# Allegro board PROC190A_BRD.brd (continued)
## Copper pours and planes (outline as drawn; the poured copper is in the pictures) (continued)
VDD_MMC0_SD on BOTTOM: 123.6,76.33 121.16,76.33 121.16,75.41 121.49,75.41 121.62,75.54 123.6,75.54
VDD_MMC0_SD on L04_PWR1: 122,76.53 121.11,76.53 120.62,76.05 120.62,75.34 119.33,74.04 114.73,74.04 113.41,75.36 111.84,75.36 111.63,75.16 111.63,73.63 112.22,73.05 120.52,73.05 122.35,74.88 122.35,76.17
VDDA1V8 on TOP: 32.14,53.62 32.14,54.51 34.19,54.51 34.34,54.66 35.1,54.66 35.48,54.28 35.48,52.93 35.64,52.78 37.19,52.78 37.62,53.21 37.62,54.12 37.78,54.28 38.9,54.28 38.96,54.22 38.96,50.6 39.57,49.99 41.25,49.99 41.5,49.73 41.5,49.02 41.33,48.84 38.33,48.84 37.64,49.53 37.64,51.55 37.27,51.92 35.43,51.92 33.73,53.62
VDDA1V8 on BOTTOM: 40.74,50.14 40.74,48.82 41.5,48.82 41.5,50.14
VDDA1V8 on L04_PWR1: 43.97,52.04 39.9,52.04 39.65,51.79 39.65,49.4 40.28,48.77 41.35,48.77 41.35,51.08 41.61,51.33 42.75,51.33 43.61,50.47 43.61,46.79 45.24,45.16 64.47,45.16 65.43,46.13 65.43,55.04 65.1,55.37 63.91,55.37 63.69,55.16 63.71,48.26 62.48,47.04 59.89,47.04 58.45,48.49 47.52,48.49
VDDA_1V8 on TOP: 41.58,54.25 41.58,52.4 41.27,52.1 41.27,51.56 41.07,51.36 39.28,51.36 39.28,54.25
VDDA_1V8 on TOP: 109.4,56.97 109.4,55.24 112.39,55.24 112.39,56.97
VDDA_1V8 on TOP: 72.11,73.03 72.44,72.69 72.44,70.61 71.78,69.95 71.78,69.01 71.96,68.83 73.46,68.83 73.94,68.35 73.94,67.67 73.36,67.08 72.9,67.08 72.62,66.8 72.62,66.14 72.82,65.94 74.07,65.94 74.55,66.42 74.55,69.22 73.2,70.56 73.2,73.13 72.95,73.38 72.95,73.71 72.69,73.96 72.21,73.96 72.11,73.86
VDDA_1V8 on BOTTOM: 69.01,75.26 68.05,75.26 68.02,75.23 68.02,74.63 68.05,74.6 68.91,74.6 69.22,74.3 69.22,72.9 69.52,72.59 72.31,72.59 72.59,72.87 73.63,72.87 74.22,72.29 78.11,72.29 78.31,72.09 78.31,71.3 78.38,71.22 78.99,71.22 79.04,71.27 79.04,72.36 78.59,72.82 74.8,72.82 73.66,73.96 71.73,73.96 71.75,73.99 71.75,74.22 71.7,74.27 71.15,74.27 71.02,74.14 71.02,73.15 70.97,73.1 69.95,73.1 69.82,73.23 69.82,74.45
VDDA_1V8 on BOTTOM: 108.58,56.85 108.58,55.58 111.3,55.58 111.3,56.85
VDDA_1V8 on BOTTOM: 63.65,66.62 64.34,65.94 73.46,65.94 73.74,66.22 73.74,66.9 72.85,67.79 69.47,67.79 69,67.32 64.83,67.32 64.66,67.5 64.66,68.14 64.41,68.38 63.78,68.38 63.65,68.25
VDDA_1V8 on BOTTOM: 58.52,78.94 57.81,78.94 57.73,78.87 57.73,78.11 57.78,78.05 57.78,77.52 57.94,77.37 58.42,77.37 58.55,77.5 58.55,78.92
VDDA_1V8 on L04_PWR1: 40.49,53.82 40.36,53.7 40.36,52.5 40.53,52.34 44.4,52.34 47.66,49.07 54.36,49.07 55.6,50.32 55.6,53.67 56.79,54.86 62.33,54.86 63.4,55.93 68.94,55.93 70.64,54.23 110.08,54.23 110.36,54.51 110.36,56.82 109.75,57.43 71.32,57.43 68.4,60.35 68.4,68.68 67.89,69.19 61.9,69.19 60.3,67.59 60.3,61.16 58.78,59.64 57.2,59.64 51.38,53.82
VDDA_1V8_FB1 on L04_PWR1: 75.03,71.3 75.03,85.12 73.53,86.61 68.76,86.61 68.12,85.98 67.49,85.98 67.06,85.55 66.57,85.55 66.57,86.79 66.7,86.92 68.1,86.92 69.34,88.16 78.05,88.16 79.04,87.17 79.04,71.3
VDDA_1V8_FB2 on L04_PWR1: 67.94,85.6 67.56,85.6 66.5,84.53 66.5,82.32 66.75,82.07 68.86,82.07 69.39,81.53 69.39,80.44 68.48,79.53 65.63,79.53 64.87,80.29 64.29,80.29 64.08,80.09 64.08,76 65.1,74.98 69.39,74.98 70.89,76.48 70.89,82.35 69.8,83.44 68,83.44 67.54,83.9 67.54,84.43 68.1,84.99 68.1,85.45
VDDA_1V8_FB3 on L03_SIG1: 62.99,81.71 62.64,81.71 62.33,81.41 62.33,65.91 63.3,65.91 63.53,66.14 63.53,81.18
VDDA_1V8_FB4 on L04_PWR1: 71.27,84.56 68.05,84.56 68.05,83.59 70.18,83.59 71.48,82.3 71.48,76.23 70.05,74.8 70.05,74.32 70.36,74.02 71.27,74.02 72.75,75.49 72.75,83.08
VDDA_1V8_FB_OSC on BOTTOM: 59.45,79.68 58.47,79.68 58.19,79.96 57.71,79.96 57.71,79.2 59.42,79.2 59.51,79.29 59.51,79.61
VDDA_ADC0 on L03_SIG1: 64.62,81.1 64.26,81.1 64.26,80.77 64.41,80.62 64.41,80.44 64.54,80.31 64.54,71.91 65.3,71.15 65.3,70.05 64.9,69.65 64.9,67.79 65.05,67.64 65.2,67.64 65.8,68.24 65.8,69.76 66.04,70 66.04,71.5 65.33,72.21 65.33,80.34 65.13,80.34 64.62,80.85
VDDA_CORE_USB on TOP: 74.07,98.15 72.64,98.15 72.64,96.27 72.78,96.13 72.78,92.65 72.9,92.53 73.28,92.53 73.46,92.71 73.46,94.13 74.07,94.74
VDDA_CORE_USB on L03_SIG1: 69.86,84.8 69.86,86.16 69.52,86.5 69.52,91.54 70.33,92.35 73.33,92.35 73.33,93.27 68.91,93.27 68.02,92.38 68.02,86.97 68.2,86.79 68.2,85.7 67.82,85.32 66.98,85.32 66.67,85.01 66.67,84.76 67.06,84.38 69.44,84.38
VDDR_CORE on TOP: 42.98,70.33 41.45,70.33 41.45,68.91 42.98,68.91
VDDR_CORE on BOTTOM: 38.45,64.38 38.45,62.18 41.27,62.18 41.27,64.38
VDDR_CORE on L03_SIG1: 64.34,82.85 64.74,82.45 67.03,82.45 67.03,84.18 66.88,84.33 66.32,84.33 66.14,84.51 66.14,85.47 66.61,85.94 67.68,85.94 67.92,86.18 67.92,86.61 67.44,87.1 67.44,88.98 67.16,89.26 65.15,89.26 64.94,89.04 64.94,87.9 64.69,87.66 63.07,87.66 61.72,86.31 60.96,86.31 60.55,86.72 60.27,86.72 59.89,87.1 57.71,87.1 57.33,86.72 54.76,86.72 54.08,86.03 54.08,84.51 54.53,84.05 58.34,84.05 58.52,84.23 63.32,84.23 63.5,84.4 63.88,84.4 64.34,83.95
VDDR_CORE on L04_PWR1: 47.04,76.15 43.21,72.31 42.62,72.31 41.53,71.22 41.53,67.89 40.69,67.06 40.69,66.08 39.32,64.71 39.32,62.69 39.88,62.13 41.43,62.13 43.43,64.14 43.43,68.5 49.53,74.6 51.16,74.6 54.94,78.38 54.94,80.44 55.88,81.38 55.88,84.84 55.65,85.06 54.18,85.06 52.83,83.72 50.16,83.72 47.04,80.59
VDDR_CORE_0V85 on BOTTOM: 36.93,65.1 36.93,65.76 37.19,66.01 41.12,66.01 41.17,65.96 41.17,64.92 41.02,64.77 38.05,64.77 37.92,64.9 37.13,64.9
VDDSHV_CANUART on TOP: 38.38,35.89 35.46,35.89 35.26,35.69 35.26,35.23 35.43,35.05 38.35,35.05 38.58,35.28 38.58,35.69
VDDSHV_CANUART on TOP: 29.59,155.78 28.91,155.78 28.75,155.63 28.75,150.88 32.23,147.4 32.74,147.4 33.07,147.73 33.07,148.29 29.69,151.66 29.69,155.68
VDDSHV_CANUART on TOP: 15.95,51.21 18.62,51.21 19.02,50.8 19.02,49.5 19,49.48 18.41,49.48 18.39,49.5 18.39,50.5 18.14,50.75 15.93,50.75 15.93,51.18
VDDSHV_CANUART on TOP: 13,51.66 13,53.09 12.85,53.24 12.27,53.24 12.12,53.09 12.12,51.77 12.22,51.66
VDDSHV_CANUART on TOP: 38.38,66.52 38.38,62.69 38.46,62.61 38.89,62.61 39.09,62.81 39.09,65.28 41.71,67.89 42.42,67.89 42.52,67.79 42.52,67.06 42.24,66.78 42.24,58.78 42.01,58.55 42.01,52.32 41.48,51.79 41.48,50.77 41.71,50.55 41.99,50.55 42.29,50.85 42.29,51.28 42.55,51.54 42.55,57.91 43.15,58.52 43.15,68.2 42.75,68.61 41.2,68.61 40.18,67.59 39.45,67.59
VDDSHV_CANUART on TOP: 29.54,159.66 31.06,159.66 31.9,160.5 32.94,160.5 33.17,160.27 33.17,159.59 32.79,159.21 29.57,159.21 29.44,159.33 29.44,159.56
VDDSHV_CANUART on TOP: 43.54,83.03 43.13,83.44 43.13,84.25 39.65,87.73 39.65,100.23 40.36,100.94 44.04,100.94 45.26,102.16 45.26,114.66 46.63,116.03 46.63,120.57 47.5,121.44 50.67,121.44 51.08,121.03 56.08,121.03 56.34,120.78 57.78,120.78 58.12,121.11 58.12,124.64 58.01,124.74 56.54,124.74 56.44,124.64 56.44,124.1 56.69,123.85 57.33,123.85 57.66,123.52 57.66,121.39 57.51,121.23 56.9,121.23 56.46,121.67 55.98,121.67 55.8,121.84 55.8,122.15 55.4,122.56 54.15,122.56 53.87,122.83 52.25,122.83 51.97,122.56 46.76,122.56 45.49,121.28 45.49,116.08 44.63,115.21 44.63,102.87 43.79,102.03 40.49,102.03 39.01,100.56 39.01,87.1 42.49,83.62 42.49,83.03 43.68,81.85 44.54,81.85 44.96,82.27 44.96,82.85 44.78,83.03
VDDSHV_CANUART on TOP: 11.1,11.89 10.41,11.89 10.36,11.84 10.36,11.02 11.18,10.21 15.88,10.21 17.96,12.29 17.96,13.34 23.52,18.9 23.52,24.38 17.37,30.53 17.37,35.26 15.47,37.16 15.47,44.93 15.85,45.31 15.85,46.96 15.67,47.14 14.76,47.14 14.61,46.99 14.61,44.6 14.81,44.4 14.81,35.2 16.74,33.27 16.74,29.97 22.78,23.93 22.78,19.81 17.04,14.07 17.04,12.47 15.42,10.85 11.46,10.85 11.1,11.2
VDDSHV_CANUART on TOP: 9.88,63.2 12.04,63.2 12.75,62.48 12.75,61.24 11.94,60.43 10.59,60.43 10.44,60.58 10.44,60.88 10.52,60.96 11.51,60.96 11.61,61.06 11.61,62.51 11.51,62.61 9.88,62.61 9.83,62.66 9.83,63.14
VDDSHV_CANUART on BOTTOM: 35.03,83.85 34.87,83.69 34.87,81.1 35,80.98 36.32,80.98 36.53,80.77 36.53,78.66 37.24,77.95 40.21,77.95 40.28,78.03 40.28,78.54 40.18,78.64 38.91,78.64 38.3,79.25 38.3,82.4 38.47,82.56 39.41,82.56 40.01,83.16 40.87,83.16 41.5,82.52 43.18,82.52 43.33,82.37 43.33,80.82 43.54,80.62 45.36,80.62 45.47,80.72 45.47,81.28 45.29,81.46 45.29,83.54 44.98,83.85
VDDSHV_CANUART on BOTTOM: 9.19,63.25 7.39,63.25 7.16,63.02 7.16,62.03 7.39,61.8 8.84,61.8 9.12,62.08 9.98,62.08 10.36,61.7 10.36,60.48 11.68,59.16 11.68,53.39 12.45,52.63 16.41,52.63 17.22,51.82 17.22,48.44 14.76,45.97 14.76,45.49 15.04,45.21 15.44,45.21 18.67,48.44 18.67,51.77 16.89,53.54 14.3,53.54 12.78,55.07 12.78,60.63 10.52,62.89 10.52,66.4 12.93,68.81 20.35,68.81 21.49,69.95 24.94,69.95 27.3,67.59 32.28,67.59 32.87,67.01 37.39,67.01 38.15,66.24 40.06,66.24 40.16,66.34 40.16,66.88 39.94,67.09 38.16,67.09 37.41,67.84 32.82,67.84 32.49,68.17 27.89,68.17 25.4,70.66 21.26,70.66 20.19,69.6 12.62,69.6 9.8,66.78 9.8,63.86
VDDSHV_CANUART on BOTTOM: 35.08,160.45 31.6,160.45 31.11,159.97 31.11,159.36 31.39,159.08 34.92,159.08 35.08,159.23
VDDSHV_CANUART on BOTTOM: 42.8,36.02 40.11,36.02 39.37,36.75 38.13,36.75 38,36.63 38,35.99 37.87,35.86 37.87,35.46 37.97,35.36 38.28,35.36 38.43,35.51 38.43,36.12 38.56,36.25 39.17,36.25 40.08,35.33 42.8,35.33
VDDSHV_CANUART on BOTTOM: 36.53,35.81 34.39,35.81 33.99,35.41 33.99,33.45 34.54,32.89 36.55,32.89 36.6,32.84 37.8,32.84 37.8,33.07 37.74,33.12 36.75,33.12 36.55,33.32 36.55,33.45 36.53,33.48 34.92,33.48 34.59,33.81 34.59,34.92 34.9,35.23 35.94,35.23 36.02,35.31 36.55,35.31 36.6,35.36 36.6,35.74
VDDSHV_CANUART on L03_SIG1: 28.47,156.29 28.47,155.4 28.88,154.99 29.95,154.99 32.79,157.84 32.79,159.59 32.04,160.34 30.84,160.34 30.03,159.53 30.03,157.84
VDDSHV_CANUART on L04_PWR1: 40.34,78.84 39.17,78.84 38.86,78.54 38.86,77.01 39.8,76.07 39.8,71.96 38.4,70.56 38.4,66.12 38.79,65.74 39.6,65.74 40.08,66.22 40.08,67.41 41.02,68.35 41.02,71.63 42.24,72.85 43,72.85 46.48,76.33 46.48,82.27 45.59,83.16 43.54,83.16 43.08,82.7 43.08,81.89 44.4,80.57 44.4,77.17 44.04,76.81 41.68,76.81 40.49,78 40.49,78.69
VDDSHV_CANUART on L04_PWR1: 41.57,50.84 41.57,50.58 41.68,50.47 41.68,48.41 40.97,47.7 40.97,35.31 41.25,35.03 42.47,35.03 42.8,35.36 42.8,38.4 43.26,38.86 43.26,46.15 42.9,46.51 42.9,50.44 42.34,51 41.73,51
VDDSHV_CANUART on L04_PWR1: 33.22,148.29 32.64,148.29 31.29,146.94 31.29,128.96 34.7,125.55 46.15,125.55 49.56,122.15 52.6,122.15 52.76,122.3 52.76,124.61 50.34,127.03 34.98,127.03 32.61,129.39 32.61,146.41 33.68,147.47 33.68,147.83
VDDSHV_SDIO on TOP: 34.52,56.47 35.21,56.47 35.41,56.26 35.41,55.12 35.26,54.97 34.16,54.97 33.89,55.25 33.89,55.5 34.29,55.91 34.29,56.24
VDDSHV_SDIO on BOTTOM: 35.56,57.28 34.37,57.28 34.37,55.52 34.8,55.09 35.56,55.09
(no net) on TOP: 1.02,1.02 1.02,175.98 125.98,175.98 125.98,1.02 ; 226 cut-outs
(no net) on BOTTOM: 1.02,1.02 1.02,175.98 125.98,175.98 125.98,1.02 ; 212 cut-outs
(no net) on L03_SIG1: 1.02,1.02 1.02,175.98 125.98,175.98 125.98,1.02 ; 204 cut-outs
ADC0_REFN on BOTTOM: 63.91,75.97 63.47,75.97 63.32,75.82 63.32,75.56 63.63,75.26 63.63,72.92 63.7,72.85 64.29,72.85 64.36,72.92 64.36,73.74 64.21,73.89 64.21,75.67
ADC0_REFP on BOTTOM: 63.37,75.31 62.99,75.31 62.61,74.93 62.61,73.69 62.76,73.53 63.3,73.53 63.45,73.69 63.45,75.23
DRAIN1 on TOP: 27.33,19.41 27.33,17.43 29.84,17.43 29.84,19.41
DRAIN1 on BOTTOM: 25.82,16.96 25.82,17.62 26.1,17.9 27.07,17.9 27.19,18.02 27.19,19.22 26.35,19.22 26.35,19.5 29.83,19.5 29.83,17.77 29.68,17.62 27.27,17.62 27.17,17.51 26.66,17.51 26.58,17.44 26.58,16.96
DRAIN2 on TOP: 30.25,19.41 30.25,17.43 33.07,17.43 33.07,19.41
DRAIN2 on BOTTOM: 33.68,16.96 33.5,17.14 33.5,17.44 33.42,17.51 33.08,17.51 32.98,17.62 30.4,17.62 30.25,17.77 30.25,19.5 33.77,19.5 33.77,19.22 32.93,19.22 32.89,19.17 32.89,17.95 33.93,17.95 34.26,17.62 34.26,17.04 34.18,16.96 ; 1 cut-out
FT4232_USB_VBUS on TOP: 55.07,4.97 55.07,6.96 54.14,7.89 54.14,8.46 50.29,8.46 49.79,8.97 49.44,8.97 49.41,8.94 49.41,8.24 48.7,8.24 48.61,8.33 48.61,8.94 48.51,9.03 48.05,9.03 47.91,8.9 47.91,7.42 48.02,7.3 52.98,7.3 53.56,6.72 53.56,5.7 54.3,4.97
LM61460_BOOT on TOP: 4.04,14.66 4.04,14.22 5.99,14.22 6.68,14.91 7.59,14.91 7.59,15.14 6.78,15.14 6.3,14.66
LM61460_FB on TOP: 9.55,14.68 9.14,14.68 9.14,13.44 9.6,12.98 9.6,11.66 9.14,11.2 7.9,11.2 7.9,10.34 9.98,10.34 10.16,10.16 10.16,9.7 10.52,9.35 11.61,9.35 11.61,9.91 11.02,9.91 9.98,10.95 9.98,13.23 9.55,13.67
LM61460_SW on TOP: 9.4,15.75 8.26,15.75 8.26,20.19 7.67,20.78 5.92,20.78 5.28,21.41 5.28,23.32 5.69,23.72 12.98,23.72 13.34,23.37 13.34,21.79 12.73,21.18 10.85,21.18 9.4,19.74
MIC1_BIAS on TOP: 59,163.4 65.63,163.4 65.89,163.65 65.89,164.11 65.74,164.26 58.85,164.26 58.75,164.16 58.75,163.65
MIC1_BIAS on TOP: 70.38,171.58 66.12,171.58 65.53,170.99 65.15,170.99 64.38,170.22 64.38,170.09 64.59,169.88 65.02,169.88 65.84,170.69 69.47,170.69 70.89,169.27 70.89,165.13 70.31,164.54 70.31,160.05 68.55,158.29 68.55,155.91 67.16,154.51 67.16,147.83 68.5,146.48 69.32,146.48 69.49,146.66 69.49,147.04 69.32,147.22 68.96,147.22 67.79,148.39 67.79,153.95 69.42,155.57 69.42,157.53 71.78,159.89 71.78,170.18
MIC1_BIAS on BOTTOM: 58.03,146.74 58.03,144.86 57.95,144.77 56.52,144.77 56.29,145 56.29,146.99 57.56,148.26 62.59,148.26 63.65,147.19 69.47,147.19 69.65,147.02 69.65,146.53 69.24,146.13 63.17,146.13 62.14,147.15 58.45,147.15
MIC1_BIAS on BOTTOM: 59.26,170.69 70.18,170.69 71.12,169.75 71.12,163.98 69.44,162.31 62.23,162.31 61.16,163.37 61.16,164.21 61.39,164.44 62.56,164.44 63.65,163.35 68.1,163.35 69.52,164.77 69.52,168.35 68.17,169.7 65.86,169.7 65.23,169.06 59.31,169.06 59.26,169.11
MIC2_BIAS on TOP: 42.88,150.37 42.88,151.41 42.67,151.61 42.67,151.99 42.77,152.1 43.21,152.1 43.36,151.94 43.36,150.44 43.28,150.37
MIC2_BIAS on TOP: 41.81,163.45 48.49,163.45 48.74,163.7 48.74,164.24 48.49,164.49 41.81,164.49 41.55,164.24 41.55,163.7
MIC2_BIAS on BOTTOM: 51.66,170.79 42.04,170.79 41.83,170.59 41.83,169.42 42.14,169.11 48.29,169.11 48.79,169.62 50.57,169.62 52.65,167.54 52.65,165.68 51.51,164.54 49.63,164.54 48.46,163.37 45.69,163.37 44.81,164.26 44.37,164.26 44.2,164.08 44.2,163.19 44.75,162.64 50.14,162.64 50.99,163.49 51.98,163.49 53.82,165.33 53.82,168.63
MIC2_BIAS on BOTTOM: 41.79,153.25 43.59,153.25 43.72,153.12 43.72,151.89 43.15,151.31 42.11,151.31 41.76,151.67 41.76,153.22
MIC2_BIAS on L03_SIG1: 43.92,160.55 42.39,159.03 42.39,151.66 42.8,151.26 43.05,151.26 43.56,151.76 43.56,158.6 45.34,160.38 45.34,164.11 45.11,164.34 45.11,165.71 48.39,168.99 48.39,170.23 48.01,170.61 45.14,170.61 43.92,169.39
PCM1_BSTOUT on TOP: 57.68,143.7 57.68,145.58 57.08,145.58 57.08,146 56.2,146 56.14,145.94 56.14,145.88 56.13,145.87 57.06,144.94 57.06,144.63 57.11,144.58 57.11,143.71 57.68,143.71
SOC_DVDD1V8 on TOP: 29.05,42.01 29.05,43.55 24.38,43.55 24.38,42.01
SOC_DVDD1V8 on L03_SIG1: 63.63,80.62 63.47,80.77 63.47,81.66 63.17,81.97 62.03,81.97 61.87,82.12 61.87,82.68 61.59,82.96 61.01,82.96 60.53,82.47 54.31,82.47 53.57,83.21 52.73,83.21 51.69,84.25 51.69,88.27 52.8,89.37 60.64,89.37 61.06,89.79 61.06,91.26 61.42,91.62 63.47,91.62 63.8,91.29 63.8,90.7 64.74,89.76 64.74,87.83 62.84,87.83 61.62,86.61 60.78,86.61 60.25,87.15 53.92,87.15 53.19,86.41 53.19,84.84 54.33,83.69 60.83,83.69 61.16,84.02 62.94,84.02 63.86,83.11 63.86,82.17 64.19,81.84 65.81,81.84 66.34,81.31 66.34,80.82 66.19,80.67 65.3,80.67 64.67,81.31 64.19,81.31 64.06,81.18 64.06,80.85 63.83,80.62
SOC_DVDD1V8 on L04_PWR1: 20.07,51.26 23.93,47.4 23.93,42.8 24.05,42.67 25.25,42.67 25.5,42.93 25.5,50.27 23.11,52.65 23.11,57.23 31.01,65.13 31.8,65.13 34.52,67.84 34.52,82.65 38.96,87.1 49.23,87.1 52.08,84.24 52.62,84.24 53.26,84.89 53.26,85.24 51.03,87.48 51.03,88.39 49.43,89.99 37.62,89.99 32.03,84.4 32.03,69.19 31.01,68.17 21.08,68.17 20.07,67.16
SOC_DVDD3V3 on TOP: 42.85,52.27 42.85,57.48 44.42,57.48 44.42,52.27
SOC_DVDD3V3 on L04_PWR1: 73.2,83.41 71.45,85.17 68.73,85.17 68.35,85.55 68.35,85.72 68.86,86.23 73,86.23 74.55,84.68 74.55,71.5 73.03,69.98 61.65,69.98 59.54,67.87 59.54,61.06 58.7,60.22 54.66,60.22 49.63,55.19 46.63,55.19 46.22,54.78 43.62,54.78 43.31,55.09 43.31,56.02 43.67,56.39 45.16,56.39 52.2,63.42 56.85,63.42 57.94,64.52 57.94,69.93 58.32,70.31 58.32,77.27 60.35,79.3 61.87,79.3 62.43,79.86 62.43,80.01 62.69,80.26 63.25,80.26 63.55,79.96 63.55,75.46 65.76,73.25 72.11,73.25 73.2,74.35
SOC_DVDD3V3_FB1 on BOTTOM: 68.83,83.95 68.83,83.31 71.45,83.31 72.29,84.15 72.29,85.22 70.41,85.22 70.41,84.07 70.28,83.95
SOC_VDD_CANUART on TOP: 51.64,79.35 51.74,79.25 51.74,78.71 47.02,78.71 46.2,77.9 46.2,76.73 44.78,76.73 44.7,76.81 44.7,79.22 44.83,79.35
SOC_VDD_CANUART on L03_SIG1: 61.93,81.28 61.42,81.28 59.13,78.99 52.68,78.99 52.22,79.45 51.26,79.45 50.98,79.17 50.98,78.28 51.41,77.85 59.84,77.85 60.17,78.18 60.17,79.2 61.37,80.39 61.93,80.39
SOC_VDDSHV5_SDIO on L03_SIG1: 69.16,84.2 68.25,84.2 68.15,84.1 68.15,82.4 66.93,81.18 66.93,80.85 66.27,80.19 66.27,74.98 67.28,73.96 67.87,73.96 68.12,74.22 68.12,74.93 67.51,75.54 67.51,79.68 69.49,81.66 69.49,83.87
SOC_VDDSHV_CANUART on BOTTOM: 53.64,82.65 53.29,82.65 53.01,82.37 50.8,82.37 50.11,81.69 47.62,81.69 47.02,82.3 47.02,82.75 47.55,83.29 47.55,84.66 46.44,85.76 35.13,85.76 33.27,83.91 33.27,81.1 33.38,81 34.47,81 34.62,81.15 34.62,83.92 34.92,84.23 45.11,84.23 45.59,83.74 45.59,81.51 47.02,80.09 50.01,80.09 51.77,81.84 53.29,81.84 53.77,82.32 53.77,82.52
SOC_VDDSHV_CANUART on L03_SIG1: 61.44,82.65 61.16,82.65 60.66,82.14 54.18,82.14 53.67,82.65 53.14,82.65 52.7,82.22 52.7,81.79 53.52,80.98 54.61,80.98 54.97,80.62 58.27,80.62 58.7,81.05 60.76,81.05 60.96,81.25 60.96,81.76 61.57,82.37 61.57,82.52
SW_2V5 on BOTTOM: 83.09,31.65 81.62,31.65 81.62,31.44 82.94,31.44 83.43,30.96 85.6,30.96 85.6,32.21 83.65,32.21
UART_SHIELD on TOP, BOTTOM, L02_GND1, L03_SIG1, L04_PWR1, L05_GND2: 62.59,3.78 62.59,1.36 62.25,1.02 51.87,1.02 51.67,1.21 51.67,6.35 52.08,6.76 52.79,6.76 53.18,6.37 53.18,4.99 53.08,4.89 53.08,3.96 53.46,3.58 58.84,3.58 59.34,4.08 59.34,4.66 59.17,4.82 59.17,6.34 59.54,6.71 60.26,6.71 61.32,5.64 61.32,4.59 61.75,4.16 62.2,4.16
USB_TYPEC1_EARTH on TOP, BOTTOM, L02_GND1, L03_SIG1, L04_PWR1, L05_GND2: 30.23,1.02 17,1.02 17,8.23 20.29,8.23 20.55,7.98 20.55,4.27 21.06,3.77 27.76,3.77 28.21,4.23 28.21,7.94 28.51,8.23 30.23,8.23
USB_TYPEC2_EARTH on TOP, BOTTOM, L02_GND1, L03_SIG1, L04_PWR1, L05_GND2: 45.23,1.02 32,1.02 32,8.23 35.29,8.23 35.55,7.98 35.55,4.27 36.06,3.77 42.76,3.77 43.21,4.23 43.21,7.94 43.51,8.23 45.23,8.23
VMAIN on TOP: 19.76,20.65 16.41,20.65 15.72,19.96 15.72,18.67 15.44,18.39 13.87,18.39 13.03,17.55 11.33,17.55 10.82,17.04 9.7,17.04 9.7,16.13 9.86,15.98 17.7,15.98 18.75,17.02 18.75,18.21 19.13,18.59 19.13,19.43 19.76,20.07
VMAIN on TOP: 28.32,160.25 27.99,160.25 27.84,160.1 27.84,159.89 27.61,159.66 26.52,159.66 26.52,159.33 27.66,159.33 27.84,159.16 27.84,158.88 27.99,158.72 28.35,158.72 28.42,158.8 28.42,160.15
VMAIN on TOP: 7.87,17.17 5.13,17.17 4.65,17.65 2.44,17.65 2.44,15.98 4.24,15.98 4.47,16.21 5.82,16.21 6.02,16.41 7.87,16.41
VMAIN on BOTTOM: 18.29,20.9 14.5,20.9 14.5,16.81 18.29,16.81
VMAIN on BOTTOM: 2.74,17.5 2.74,14.96 9.32,14.96 9.32,17.5
VMAIN on BOTTOM: 28.52,160.2 28.07,160.2 27.61,159.74 26.82,159.74 26.72,159.64 26.72,158.98 27,158.7 28.45,158.7 28.52,158.78
VMAIN on L04_PWR1: 17.63,20.17 13.44,20.17 10.21,23.39 10.21,44.53 5.33,49.4 5.33,103.43 3.07,105.69 3.07,138.91 19.71,155.55 25.73,155.55 29.03,158.85 29.03,166.17 28.19,167 9.3,167 1.24,158.95 1.24,16.43 2.92,14.76 17.17,14.76 17.63,15.21
VMAIN_PD on TOP: 27.45,13.84 27.45,14.86 27.88,15.29 27.88,16.31 27.93,16.36 28.77,16.36 28.82,16.31 28.82,14.97 28.66,14.81 28.66,13.84
VMAIN_PD on TOP: 32.54,14.01 32.54,16.25 32.67,16.38 34.7,16.38 34.83,16.26 34.83,15.7 35.24,15.28 35.24,14.01
VMAIN_PD on TOP: 18.97,24.75 16.97,24.75 16.97,22.96 17.06,22.87 17.59,22.87 18.26,22.2 19.51,22.2 19.51,23.28 19,23.79 19,24.72
VMAIN_PD on BOTTOM: 28.85,17.48 28.12,17.48 28.09,17.45 28.09,16.43 27.89,16.23 27.89,14.99 27.94,14.94 28.78,14.94 28.85,15.01
VMAIN_PD on BOTTOM: 32.13,16.59 32.13,17.41 32.82,17.41 33.6,16.64 34.41,16.64 34.59,16.46 34.59,15.57 34.41,15.39 32.68,15.39 32.53,15.54 32.53,16.19
VMAIN_PD on L03_SIG1: 34.82,16.94 32.38,16.94 32.31,16.87 32.31,15.42 31.7,14.81 29.64,14.81 28.98,15.47 28.98,16.64 25.96,16.64 25.55,16.23 22.96,16.23 22.35,16.84 22.35,22.63 22.81,23.09 22.81,24.49 22.56,24.74 13.51,24.74 12.9,24.13 12.9,12.88 14.38,11.4 25.07,11.4 25.96,10.52 33.4,10.52 34.82,11.94
VPP_1V8 on TOP: 53.64,66.19 54.36,66.19 54.58,65.96 55.83,65.96 56.06,65.74 56.06,65.43 55.7,65.07 53.67,65.07 53.64,65.1
VPP_1V8 on L03_SIG1: 60.63,79.17 60.63,78.21 59.56,77.14 59.56,70.43 55.7,66.57 55.68,66.57 55.58,66.47 55.58,65.56 55.7,65.43 56.85,65.43 61.16,69.75 61.16,76.05 61.9,76.78 61.9,79.53 62.1,79.73 62.1,80.09 61.7,80.09 61.65,80.04 61.65,79.93 61.42,79.71 61.16,79.71
VPP_SUPPLY on TOP: 51.94,61.82 51.08,61.82 51.05,61.85 51.05,63.02 51.59,63.55 51.59,66.14 51.69,66.24 52.86,66.24 53.01,66.09 53.01,65.2 52.73,64.92 52.25,64.92 52.12,64.8 52.12,62.71 51.94,62.53
XDS_SHIELD on TOP, BOTTOM, L02_GND1, L03_SIG1, L05_GND2: 1.06,45.29 6.48,45.29 6.89,45.7 6.89,46.83 6.54,47.17 5.06,47.17 4.82,46.93 4.14,46.93 3.78,47.28 3.78,52.72 4.08,53.02 4.9,53.02 4.96,52.96 6.31,52.96 6.75,53.39 6.75,54.11 6.29,54.57 1.06,54.57
XDS_SHIELD on BOTTOM: 4.84,58.7 4.85,58.69 4.85,55.4 4.87,55.38 4.87,54.57 6.29,54.57 6.75,54.11 6.75,53.39 6.31,52.96 4.96,52.96 4.9,53.02 4.08,53.02 3.78,52.72 3.78,47.28 4.14,46.93 4.82,46.93 5.06,47.17 6.54,47.17 6.89,46.83 6.89,45.7 6.48,45.29 1.02,45.29 1.02,58.02 1.7,58.7
XDS_USB_VBUS on TOP: 5,51.03 6.35,51.03 7.16,51.84 8.48,51.84 8.99,51.33 8.99,50.6 9.07,50.52 10.26,50.52 10.72,50.98 10.72,52.58 10.69,52.6 5.31,52.6 5,52.3
XDS_USB_VBUS on TOP: 18.8,76.07 18.8,75.03 18.85,74.98 20.32,74.98 20.62,74.68 20.62,74.17 21.47,74.17 21.41,74.23 21.41,75.77 20.22,75.77 19.68,76.3 19.02,76.3
XDS_USB_VBUS on BOTTOM: 18.01,82.73 17.42,82.73 17.2,82.5 17.2,80.82 18.08,79.93 20.57,79.93 20.78,80.14 20.78,80.47 20.52,80.72 18.52,80.72 18.08,81.15 18.08,82.65
XDS_USB_VBUS on BOTTOM: 9.93,50.7 9.32,51.31 9.32,57.51 2.03,64.8 2.03,72.59 2.84,73.41 10.87,73.41 12.67,75.21 21.46,75.21 21.46,73.48 19.86,73.48 18.85,72.47 18.85,71.6 11.56,71.6 11.02,72.14 4.9,72.14 3.96,71.2 3.96,64.64 11.07,57.53 11.07,50.88 10.9,50.7
N24605846 on TOP: 55.49,146.36 55.49,143 56.82,143 56.82,144.81 55.96,145.67 55.96,147.39 55.5,147.39 55.5,146.36
N25809420 on TOP: 72.13,42.98 72.87,42.24 72.87,38.69 72.97,38.58 72.97,36.32 73.63,35.66 81.15,35.66 82.75,37.26 82.75,38.68 82.75,38.69 82.75,42.59 83.13,42.98 85.32,42.98 85.32,36.73 82.52,33.93 72.03,33.93 70.59,35.38 70.59,42.98
N25809420 on BOTTOM: 83.11,41.26 86.09,41.26 86.09,38.64 83.21,38.64 83.21,40.46 82.94,40.73 82.94,41.08
N25815350 on TOP: 104.62,43.2 105.3,42.53 105.3,38.14 104.19,37.03 104.19,35 105.28,33.91 113.28,33.91 115.18,35.8 115.18,42.68 115.56,43.07 117.93,43.07 117.93,36.02 114.45,32.54 104.57,32.54 102.54,34.57 102.54,43.2
N25815350 on BOTTOM: 102.88,41.26 104.96,41.26 105.1,41.13 105.1,40.29 104.72,39.91 104.72,38.71 104.59,38.58 103.03,38.58 102.8,38.81 102.8,39.5 102.65,39.65 102.65,41.03
N27162147 on BOTTOM: 43.1,14.24 43.1,15.53 43.27,15.7 45.53,15.7 45.53,18.23 42.54,18.23 42.51,18.21 42.51,14.24
N27162183 on TOP: 41.01,15.7 41.01,13.92 46.05,13.92 46.05,15.7
N27162183 on BOTTOM: 39.84,15.4 39.84,16.44 42.09,16.44 42.21,16.32 42.21,14 40.96,14 40.96,14.46 40.02,15.4
N27162293 on BOTTOM: 39.53,15.28 39.53,16.36 36.43,16.36 36.43,15.37 36.53,15.28
N27175987 on TOP: 81.03,57.52 82.42,57.52 82.72,57.22 83.43,57.22 83.6,57.39 83.6,59.79 83.47,59.92 82.89,59.92 82.85,59.88 82.85,58.65 82.51,58.31 81.07,58.31 81.01,58.25 81.01,57.54
N27224561 on TOP: 43.83,150.41 43.83,151.36 43.92,151.44 43.92,152.2 42.82,153.29 42.82,154.84 44.37,154.84 44.37,150.39 43.85,150.39 43.85,150.41

Small or netless copper shapes (teardrops, artwork), in the pictures only: 19 on TOP, 23 on BOTTOM, 23 on L03_SIG1

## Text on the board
Ref Des/Assembly Bottom: A | BOTTOM  ASSEMBLY OF PROC190A
Ref Des/Silkscreen Bottom: A | uSD_CONN | ASSY# | FOR EVALUATION ONLY; | NOT FCC APPROVED FOR RESALE
User.Comments: BOARD NAME: | AM275 EVM | REV: A | DATE: 28/02/25 | DESCRIPTION: | SHEET | OF | 13 | PROC190A | SCALE: 1 | TEXAS INSTRUMENTS
Ref Des/Assembly Top: TOP ASSEMBLY OF PROC190A
Ref Des/Silkscreen Top: JTAG_CONN | VCC3V3_XDS | AEC2 | SOC_DVDD1V8 | CAN_WKUP_HDR | INT | DGND | VDD_CORE | VBUS_TYPEC1 | WAIT-IN-RESET | PMIC_CORE_CONFIG | MCU_RESETz | VDDR_CORE_PWR_LED | VCC_3V3_SYS_PWR_LED | SOC_VDDSHV_CANUART | CORE_CONFIG | PMIC_RSTOUT_LED | VDDR_CORE | MCU WARM RST | SOC_DVDD3V3 | PMIC_RSTOUT | LINE_IN_2 | VCC_5V0 | VPP_1V8 | UART_CONN | BOOTMODEON_HDR | LINE_IN_1 | LINE_OUT_1 | RESETSTATZ_1V8 | ETHO_CONN | MCU_PORZ_HDR | PORz | LINE_OUT_2 | MMC0_SEL | MLB_HDR | VDD_2V5 | ADC_REFP_VSEL | ETH1_CONN | AEC1 | VDD_MMC0_SD | ADC0_HDR | PMIC_LPM_SEL | PD_PGM | USB-C PWR | MCAN0_HDR | VBUS_TYPEC1_PWR_LED | XDS_USB_VBUS | PWR ERROR | INDICATION LED | JTAG_CTI | VBUS_TYPEC2_PWR | EEPROM_WP_HDR | FT_PWREN#_LED | VBUS_TYPEC2 | VDDA_1V8 | USB-C DRP | IO RET WAKE | SOC_VDD_CANUART | VBAT_IN | BMODE 0-7 | SoC_GPIO_LED | IO EXP GPIO LED | BMODE 8-15 | MLB_VSEL_HDR | AUDIO-AM275-EVM | PROC190A | AM275 EVM | SL# | OPN#
PAGE_OUTLINE: 16. | 17. | ENSURE UL REGISTERED E-FILE NUMBER SHALL BE PRINTED ON THE PCB SILKSCREEN. | VIA ON PAD SHALL BE TYPE-VI FILLED. | REVIEWED BY | APPROVED BY | LAYOUT BY | SIGNATURES | UD | ZA | PANDI | 280225 | DATE | SIZE | SCALE: | D | NONE | SHEET 1 OF 23 | PROC190A | Rev | A | TEXAS INSTRUMENTS | AM275 EVM
User.12: R33 | C26 | H3 | H4 | R21 | R22 | R24 | R25 | R27 | R28 | R30 | J40 | R31 | R15 | R13 | R16 | R14 | R3 | R1 | R4 | R2 | R18 | C23 | C22 | R17 | C17 | R19 | C24 | C25 | R20 | R23 | R26 | R29 | R32 | 8
User.13: ASSEMBLY_BOTTOM | BOTTOM ASSEMBLY OF PROC167A
User.15: SECONDARY-SIDE-SIG | 11
User.16: BOARD NAME: | AM62D EVM  BOARD | REV: E1 | DATE: 29/04/24 | DESCRIPTION: | SHEET | OF | 15 | PROC180E1 | SCALE: 1 | TEXAS INSTRUMENTS
User.18: J1 | R75 | R30 | C73 | C104 | C110 | C52 | C109 | C51 | C46 | C114 | C56 | C15 | C25 | C83 | LBL1 | TP28 | TP7 | TP8 | TP24 | TP12 | TP23 | TP18 | TP2 | TP25 | TP19 | C47 | C105 | TP17 | TP1 | TP3 | TP11 | C68 | C10 | C54 | C76 | C18 | C75 | C17 | C80 | C22 | C77 | C74 | C16 | C19 | R36 | R81 | R79 | R34 | R31 | R26 | R76 | R71 | C14 | C7 | C72 | C65 | C112 | C23 | C94 | C36 | C81 | C69 | C55 | C11 | C113 | C82 | C24 | C37 | C95 | Bottom Overlay | Bottom Solder | M1 Board Outline | TEXAS INSTRUMENTS | Not in version control | SVN REV: | .PCB_Rev | 15:44:36 | REV: | 22-07-2024 | .PRJ_Number | GENERATED    : | BOARD #: | .VariantName | Plot_File_Name is not interpreted until output | ASSEMBLY VARIANT: | COMPONENTS MARKED 'DNP' SHOULD NOT BE POPULATED. | PCB VIEWED FROM BOTTOM SIDE | PLOT NAME = | For evaluation only; not FCC approved for resale.
User.19: 80 | 2 | 79
User.45: 03 | 04 | 05 | 06 | STRIPLINE | MICROSTRIP | EDGE COUPLED STRIPLINE | EDGE COUPLED MICROSTRIP | L1 | L3 | L1,L6 | 5.8 | 5 | 3.7 | 4.2 | 3.6 | 6 | 4.4 | 8 | NA | 120 | 90 | 50 | L2 | L2,L5 | FIGURE | FINISHED_SIZE | 8.0 | 36.0 | 40.0 | 44.0 | 60.0 | 32.0 | 108.0 | 126.0 | 48.0x22.0 | 62.0x24.0 | 68.0x34.0 | 82.0x24.0 | 158.0x78.0 | ROTATION | - | 90.000 | 0.000 | DRILL CHART: TOP to BOTTOM | ALL UNITS ARE IN MILS | TOLERANCE_DRILL | +3.0/-3.0 | +3.0/-2.0 | +2.0/-2.0 | TOLERANCE_TRAVEL | PLATED | NON-PLATED | QTY | 2913 | 3 | 12 | 15 | 11 | 24 | 34 | 4 | 2 | REV # | SCALE:NONE | SIZE | DESCRIPTION | FILE NAME: | REVISIONS | CCN # | DRAWING NO. | DDMMYY | DATE | OF | REV | SHEET | 01 | 02 | D | FY10XXXX5200X0X | *
